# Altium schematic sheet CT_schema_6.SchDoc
size 278 x 170 mm
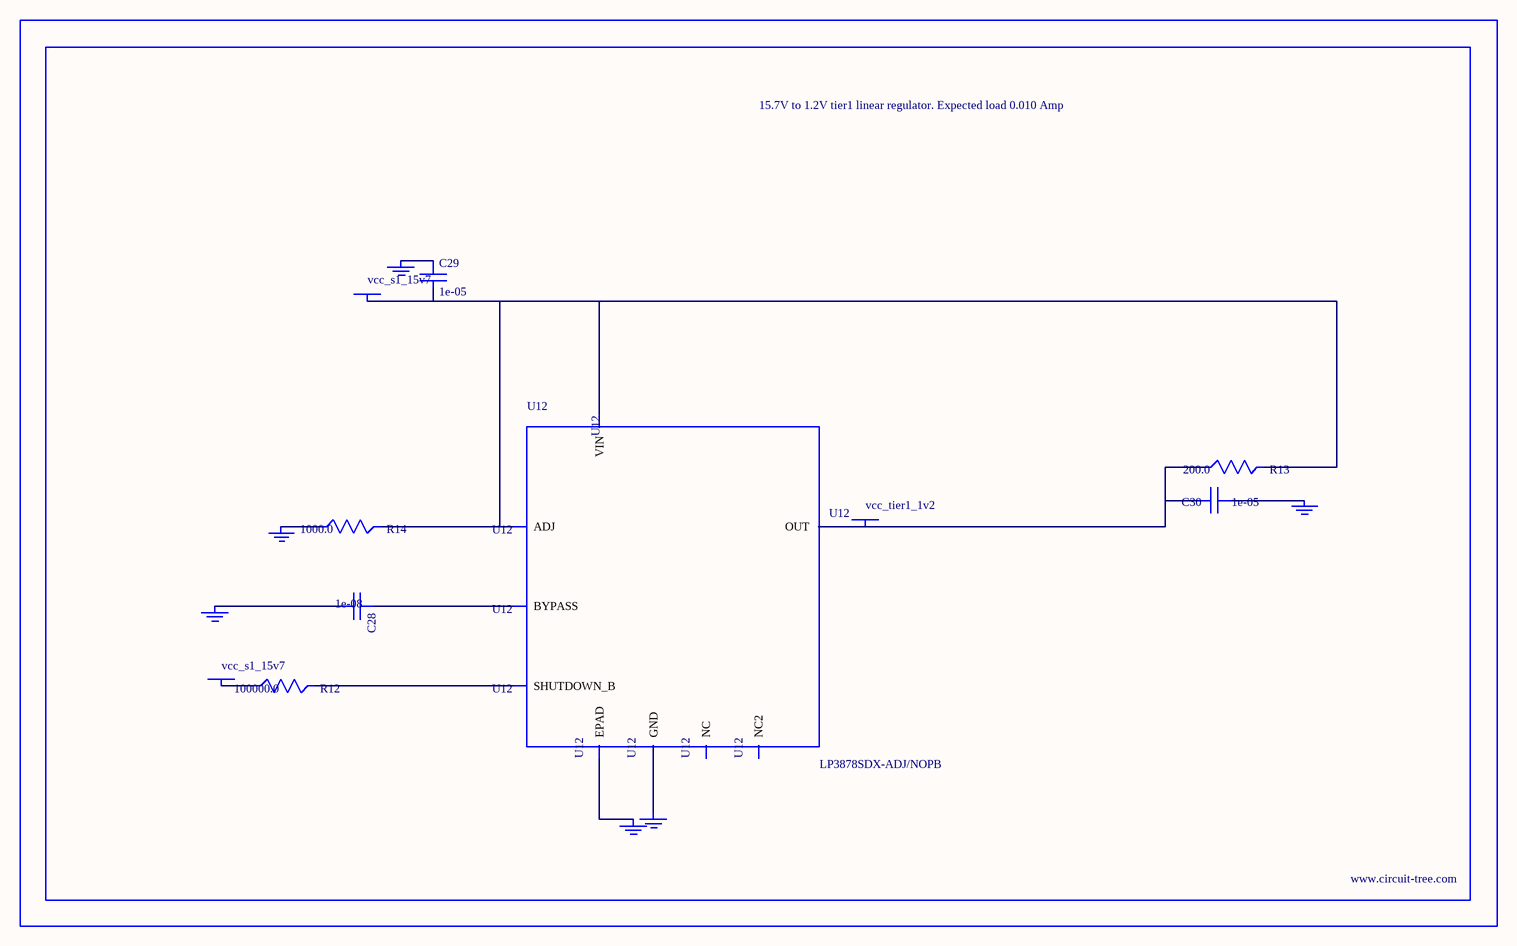
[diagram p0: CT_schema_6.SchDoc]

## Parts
BORDER5  (no value)
C28  1e-08  [C0402]
C29  1e-05  [C1210]
C30  1e-05  [C0805]
GND_INSTANCE_5_0  (no value)
GND_INSTANCE_5_1  (no value)
GND_INSTANCE_5_2  (no value)
GND_INSTANCE_5_3  (no value)
GND_INSTANCE_5_4  (no value)
GND_INSTANCE_5_5  (no value)
POWER_INSTANCE_5_0  vcc_s1_15v7
POWER_INSTANCE_5_1  vcc_s1_15v7
POWER_INSTANCE_5_2  vcc_tier1_1v2
R12  100000.0  [R0603]
R13  200.0  [R0603]
R14  1000.0  [R0603]
U12  LP3878SDX-ADJ/NOPB  [WSON-8]

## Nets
NetC28_1: C28.1 U12.1(BYPASS)
NetC28_2: C28.2 GND_INSTANCE_5_0.0(GND)
NetC29_1: C29.1 GND_INSTANCE_5_1.0(GND)
NetC29_2: C29.2 POWER_INSTANCE_5_0.0(PWR) R13.2 R14.2 U12.4(VIN) U12.6(ADJ)
NetC30_1: C30.1 GND_INSTANCE_5_2.0(GND)
NetC30_2: C30.2 POWER_INSTANCE_5_2.0(PWR) R13.1 U12.5(OUT)
NetGND_INSTANCE_5_3_0: GND_INSTANCE_5_3.0(GND) R14.1
NetGND_INSTANCE_5_4_0: GND_INSTANCE_5_4.0(GND) U12.PAD(EPAD)
NetGND_INSTANCE_5_5_0: GND_INSTANCE_5_5.0(GND) U12.3(GND)
NetPOWER_INSTANCE_5_1_0: POWER_INSTANCE_5_1.0(PWR) R12.1
NetR12_2: R12.2 U12.8(SHUTDOWN_B)

Not connected (* = marked no-connect by the designer): U12 2(NC) 7(NC2)

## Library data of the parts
BORDER5 = BORDER_PAGE5
C28 = C0402C103K3RAC
C29 = C1210C106K5PACTU
C30 = GRM219R60J106ME19D
GND_INSTANCE_5_0-GND_INSTANCE_5_5 = GND
POWER_INSTANCE_5_0-POWER_INSTANCE_5_2 = PWR
R12 = RC0603JR-07100KL
R13 = RC0603JR-07200RL
R14 = RC0603JR-071KL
